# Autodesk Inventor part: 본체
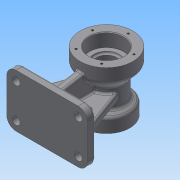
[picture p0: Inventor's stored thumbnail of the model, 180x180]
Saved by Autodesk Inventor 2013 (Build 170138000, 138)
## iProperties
Created: 2015-08
Part Number: 본체
Material: 일반
Document SubType Name: Modeling
Designer: Administrator
Density: 1 g/cm^3
Author: Administrator
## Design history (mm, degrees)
sketch "스케치1"
  geometry: L1 (0, 0)-(0, -90); L2 (0, 0)-(40, 0); L3 (40, 0)-(40, -20); L4 (40, -20)-(26, -36.685); L5 (26, -36.685)-(26, -64.804); L6 (26, -64.804)-(35, -70); L7 (35, -70)-(35, -90); L8 (35, -90)-(0, -90); 1 further point
  constraints: 16 end point, 3 perpendicular, 2 parallel, 1 coincident, 1 vertical
  dimensions: "d9" = 90 distance of L1.start L1.end; "d10" = 70 diameter of L7 L1; "d11" = 52 diameter of L5 L1; "d12" = 80 diameter of L3 L1; "d13" = 20 distance of L2.end L3.end; "d14" = 20 distance of L6.end L7.end; "d15" = 40 deg angle of L3 L4; "d16" = 60 deg angle of L7 L6
revolve "회전1" sketch "스케치1" stored, may be unused: angle "d17" = 90 deg
sketch "스케치2"
  geometry: L1 (-40, 0)-(40, 0) reference; L2 (40, 0)-(40, -20) reference; L3 (40, -20)-(26, -36.685) reference; L4 (26, -36.685)-(26, -64.804) reference; L5 (26, -64.804)-(35, -70) reference; L6 (35, -70)-(35, -90) reference; L7 (35, -90)-(-35, -90) reference; L8 (-35, -90)-(-35, -70) reference; L9 (-35, -70)-(-26, -64.804) reference; L10 (-26, -64.804)-(-26, -36.685) reference; L11 (-26, -36.685)-(-40, -20) reference; L12 (-40, -20)-(-40, 0) reference; L13 (-78, -90)-(-90, -90); L14 (-90, -90)-(-90, -10); L15 (-90, -10)-(-78, -10); L16 (-78, -10)-(-78, -90); 1 further point
  constraints: 8 end point, 2 parallel, 1 collinear, 1 horizontal, 1 perpendicular
  dimensions: "d18" = 12 distance of L14.end L15.end; "d19" = 80 distance of L13.end L14.end; "d20" = 90 distance from line of point (0, 0) L14
extrude "돌출1" join sketch "스케치2" stored distance "d21" = 122; taper "d22" = 0 deg
fillet "모깎기4" dims "d98" = 5
sketch "스케치3"
  geometry: L1 (-40, 0)-(40, 0) reference; L2 (40, 0)-(40, -18.18) reference; L3 (35, -72.887)-(35, -90) reference; L4 (35, -90)-(-35, -90) reference; L5 (-35, -90)-(-35, -72.887) reference; L6 (-40, -18.18)-(-40, 0) reference; L7 (-90, -90)-(-90, -10) reference; L8 (-90, -10)-(-78, -10) reference; L9 (-78, -10)-(-78, -90) reference; L10 (-78, -90)-(-90, -90) reference; L11 (-35, -80)-(-78, -80); L12 (-40, -13.3)-(-78, -20); L13 (38.83, -21.394)-(27.17, -35.29) reference; L14 (26, -38.504)-(26, -61.917) reference; L15 (28.5, -66.247)-(32.5, -68.557) reference; L16 (-32.5, -68.557)-(-28.5, -66.247) reference; L17 (-26, -61.917)-(-26, -38.504) reference; L18 (-27.17, -35.29)-(-38.83, -21.394) reference; L19 (-22.763, -10.26)-(-22.763, -80); L20 (-40, -13.3)-(-22.763, -10.26); L21 (-35, -80)-(-22.763, -80); A1 r 5 centre (35, -18.18) between (38.83, -21.394) and (40, -18.18) reference; A2 r 5 centre (31, -38.504) between (27.17, -35.29) and (26, -38.504) reference; A3 r 5 centre (31, -61.917) between (26, -61.917) and (28.5, -66.247) reference; A4 r 5 centre (30, -72.887) between (35, -72.887) and (32.5, -68.557) reference; A5 r 5 centre (-30, -72.887) between (-32.5, -68.557) and (-35, -72.887) reference; A6 r 5 centre (-31, -61.917) between (-28.5, -66.247) and (-26, -61.917) reference; A7 r 5 centre (-31, -38.504) between (-26, -38.504) and (-27.17, -35.29) reference; A8 r 5 centre (-35, -18.18) between (-40, -18.18) and (-38.83, -21.394) reference; 1 further point
  constraints: 10 end point, 4 point on line, 2 parallel, 1 collinear, 1 perpendicular
  dimensions: "d23" = 10 distance between parallel lines of L11 L10; "d24" = 10 distance from line of L8 L12.end; "d25" = 80 deg angle of L9 L12; "d99" = 69.73972 distance of L19.start L19.end
extrude "돌출4" join sketch "스케치3" stored distance "d100" = 12; taper "d101" = 0 deg
node "작업 평면1"
sketch "스케치4"
  geometry: L1 (0, 0)-(0, 12) reference; L2 (0, 12)-(55, 12) reference; L3 (67, 12)-(122, 12) reference; L4 (122, 12)-(122, 0) reference; L5 (122, 0)-(0, 0) reference; L6 (112, 12)-(86.091, 83.185); L7 (55, 12)-(55, 64.702) reference; L8 (67, 64.702)-(67, 12) reference; A1 r 26 centre (61, 90) between (67, 64.702) and (55, 64.702) reference; 1 further point
  constraints: 2 end point, 1 point on circle, 1 point on line
  dimensions: "d29" = 10 distance from line of L4 L6.start; "d30" = 70 deg angle of L3 L6
feature "리브1" sketch "스케치4" dims "d31" = 1, "d32" = 12, "d33" = 0, "d34" = 0, "d35" = 1, "d36" = 1
fillet "모깎기1" dims "d37" = 14
sketch "스케치5"
  geometry: A1 r 14 centre (0, 66) between (0, 80) and (-14, 66) reference; A2 r 14 centre (0, 14) between (-14, 14) and (0, 0) reference; A3 r 14 centre (94, 14) between (94, 0) and (108, 14) reference; A4 r 14 centre (94, 66) between (108, 66) and (94, 80) reference; 5 further points
  constraints: 4 coincident
hole "구멍1" sketch "스케치5" at (0, 66), (94, 66), (94, 14), (0, 14) diameter "d38" = 12; stored, may be unused: countersink angle "d42" = 90 deg, drill point angle "d44" = 0 deg; dims "d39" = 6, "d40" = 4, "d41" = 2, "d43" = 8
hole "구멍2" diameter "d47" = 38; stored, may be unused: countersink angle "d51" = 90 deg, drill point angle "d53" = 0 deg; dims "d45" = 10, "d46" = 10, "d48" = 6, "d49" = 52, "d50" = 20, "d52" = 23
hole "구멍3" diameter "d56" = 32; stored, may be unused: countersink angle "d60" = 90 deg, drill point angle "d62" = 0 deg; dims "d54" = 10, "d55" = 10, "d57" = 6, "d58" = 40, "d59" = 17, "d61" = 23
sketch "스케치6"
  geometry: C1 r 20 at (0, 0) reference; 1 further point
  constraints: 1 vertical alignment
  dimensions: "d63" = 27 distance of C1.centre point (0, 27)
hole "구멍4" sketch "스케치6" at (0, 27) diameter "d64" = 3.242; stored, may be unused: countersink angle "d68" = 90 deg, drill point angle "d70" = 118 deg; dims "d65" = 10, "d66" = 40, "d67" = 17, "d69" = 13
sketch "스케치7"
  geometry: C1 r 26 at (0, 0) reference; 1 further point
  constraints: 1 vertical alignment
  dimensions: "d74" = 33 distance of C1.centre point (0, 33)
hole "구멍5" sketch "스케치7" at (0, 33) diameter "d75" = 3.242; stored, may be unused: countersink angle "d79" = 90 deg, drill point angle "d81" = 118 deg; dims "d76" = 10, "d77" = 40, "d78" = 17, "d80" = 13
sketch "스케치8"
  geometry: L1 (21, 24)-(21, 18); L2 (33, 24)-(33, 18); L3 (-10, 0)-(4, 0) reference; A1 r 26 centre (51, 78) between (25.909, 71.185) and (45, 52.702) reference; A2 r 6 centre (27, 24) between (33, 24) and (21, 24); A3 r 6 centre (27, 18) between (21, 18) and (33, 18); 1 further point
  constraints: 4 end point, 4 point on circle, 3 tangent, 2 centre point, 1 parallel, 1 vertical alignment
  dimensions: "d85" = 12 diameter of A2; "d86" = 12 diameter of A3; "d87" = 18 dimension on A3 A2; "d89" = 18 distance from line of A3.centre L3; "d102" = 24 horizontal distance of A1.centre A3.centre
extrude "돌출3" cut sketch "스케치8" distance "d90" = 12; taper "d91" = 0 deg
chamfer "모따기1" distance "d92" = 1; stored, may be unused: second distance "d93" = 2, angle "d94" = 45 deg
fillet "모깎기2" dims "d95" = 0.3, "d96" = 3
fillet "모깎기3" dims "d97" = 3
fillet "모깎기5" dims "d103" = 3
fillet "모깎기6" dims "d104" = 3
fillet "모깎기7" dims "d105" = 3
sketch "스케치10"
  geometry: L1 (-24, -78)-(-76, -78) reference; L2 (-80, -37.881)-(-80, -75) reference; 2 further points
  constraints: 1 other
  dimensions: "d106" = 24 distance from line of point (-64, -54) L1; "d107" = 16 distance from line of point (-64, -54) L2
feature "엠보싱1" sketch "스케치10" dims "d9" = 90, "d10" = 70, "d11" = 52, "d12" = 80, "d13" = 20, "d14" = 20, "d15" = 40 deg, "d16" = 60 deg, "d108" = 0.5, "d109" = 0
node "솔리드1"
mirror "대칭1"
pattern_circular "원형 패턴1" dims angle "d72" = 360 deg
pattern_circular "원형 패턴2" dims angle "d83" = 360 deg
mirror "대칭2"
node "절단 모서리 투영1"
node "절단 모서리 투영2"
node "절단 모서리 투영3"
